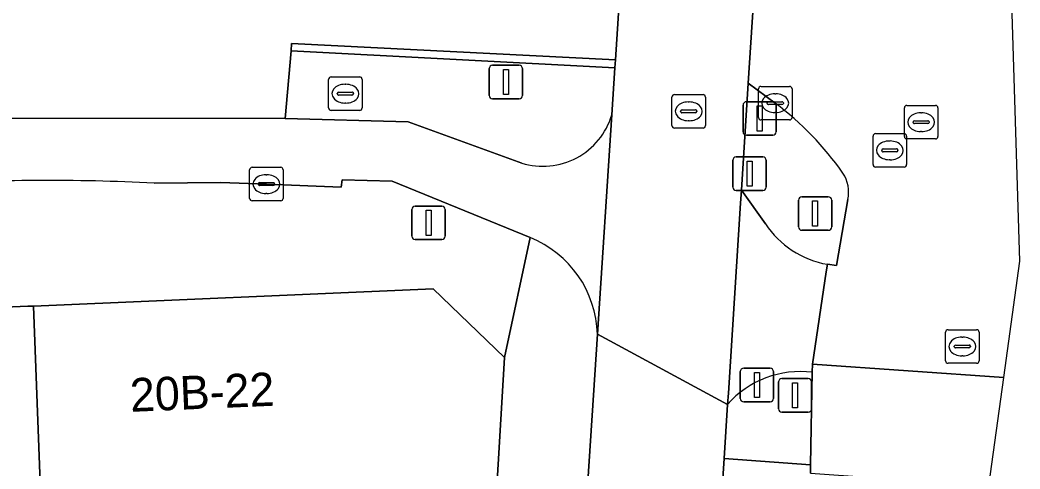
# Model space of a CAD drawing. Extents: x 161087 to 161926, y 382572 to 383873.
# Drawn here: x 161847.36 to 161877.19, y 382826.69 to 382840.09 of the extents above; entities that cross this region are included whole.
import ezdxf

# ---------------------------------------------------------------- set-up
doc = ezdxf.new("R2010")
doc.units = 0
for name, color, linetype in [('IMGEO_Berm_groen', 7, 'Continuous'), ('IMGEO_Drukknoppaal', 7, 'Continuous'), ('IMGEO_Fietspad_gesloten', 7, 'Continuous'), ('IMGEO_Kolk', 7, 'Continuous'), ('IMGEO_Lichtmast', 7, 'Continuous'), ('IMGEO_Pand', 7, 'Continuous'), ('IMGEO_Pand_nummerreeks', 7, 'Continuous'), ('IMGEO_Portaal', 7, 'Continuous'), ('IMGEO_Rijbaan_lokaal_gesloten', 7, 'Continuous'), ('IMGEO_Rijbaan_lokaal_open', 7, 'Continuous'), ('IMGEO_Rioolput', 7, 'Continuous'), ('IMGEO_Verkeerseiland_gesloten', 7, 'Continuous'), ('IMGEO_Verkeerseiland_open', 7, 'Continuous'), ('IMGEO_Verkeersregelinstallatiepaal', 7, 'Continuous'), ('IMGEO_Voetpad_open', 7, 'Continuous')]:
    doc.layers.add(name, color=color, linetype=linetype)

msp = doc.modelspace()

# ---------------------------------------------------------------- linework, layer by layer
at = {"layer": 'IMGEO_Berm_groen'}
msp.add_lwpolyline([(161870.941, 382826.561), (161870.946, 382826.819), (161868.362, 382827.004), (161866.09, 382792.42), (161866.022, 382791.413), (161868.117, 382791.28), (161868.615, 382791.249), (161868.901, 382795.776), (161869.763, 382809.058)], dxfattribs=at)
at = {"layer": 'IMGEO_Drukknoppaal'}
for p, q in [((161868.629, 382835.1), (161868.629, 382835.9)), ((161868.629, 382835.9), (161868.629, 382835.1)), ((161868.729, 382836), (161869.519, 382836)), ((161869.519, 382836), (161868.729, 382836)), ((161869.619, 382835.9), (161869.619, 382835.1)), ((161869.619, 382835.1), (161869.619, 382835.9)), ((161869.519, 382835), (161868.729, 382835)), ((161868.729, 382835), (161869.519, 382835)), ((161868.949, 382829.695), (161869.739, 382829.695)), ((161869.739, 382829.695), (161868.949, 382829.695)), ((161868.849, 382828.795), (161868.849, 382829.595)), ((161868.849, 382829.595), (161868.849, 382828.795)), ((161869.839, 382829.595), (161869.839, 382828.795)), ((161869.839, 382828.795), (161869.839, 382829.595)), ((161869.739, 382828.695), (161868.949, 382828.695)), ((161868.949, 382828.695), (161869.739, 382828.695))]:
    msp.add_line(p, q, dxfattribs=at)
for points in [[(161869.049, 382835.875), (161869.199, 382835.875), (161869.199, 382835.125), (161869.049, 382835.125), (161869.049, 382835.875)], [(161869.269, 382829.57), (161869.419, 382829.57), (161869.419, 382828.82), (161869.269, 382828.82), (161869.269, 382829.57)]]:
    msp.add_lwpolyline(points, dxfattribs=at)
for centre, start, end in [((161868.729, 382835.9), 90, 180), ((161868.729, 382835.9), 90, 180), ((161869.519, 382835.9), 0, 90), ((161869.519, 382835.9), 360, 90), ((161868.729, 382835.1), 180, 270), ((161868.729, 382835.1), 180, 270), ((161869.519, 382835.1), 270, 0), ((161869.519, 382835.1), 270, 0), ((161868.949, 382829.595), 90, 180), ((161868.949, 382829.595), 90, 180), ((161869.739, 382829.595), 0, 90), ((161869.739, 382829.595), 360, 90), ((161868.949, 382828.795), 180, 270), ((161868.949, 382828.795), 180, 270), ((161869.739, 382828.795), 270, 0), ((161869.739, 382828.795), 270, 0)]:
    msp.add_arc(centre, 0.1, start, end, dxfattribs=at)
at = {"layer": 'IMGEO_Fietspad_gesloten'}
for points in [[(161867.147, 382869.551), (161866.618, 382861.706), (161865.956, 382851.636), (161865.566, 382845.696), (161865.461, 382844.092), (161865.445, 382843.847), (161865.12, 382838.895), (161865.105, 382838.659), (161865.013, 382837.253), (161864.583, 382830.709), (161868.468, 382828.616), (161868.493, 382828.949), (161868.857, 382834.621), (161868.883, 382835.013), (161869.087, 382838.199), (161869.439, 382843.669), (161869.49, 382844.463)], [(161869.599, 382834.003), (161868.883, 382835.013), (161868.857, 382834.621), (161868.493, 382828.949), (161868.468, 382828.616)], [(161871.412, 382832.571), (161871.446, 382832.798)], [(161870.997, 382829.577), (161871.001, 382829.815), (161871.412, 382832.571)], [(161862.676, 382741.127), (161863.359, 382751.101), (161864.144, 382763.393), (161864.145, 382763.415), (161865.585, 382784.899), (161866.022, 382791.413), (161866.09, 382792.42), (161868.362, 382827.004), (161868.468, 382828.616), (161864.583, 382830.709), (161862.087, 382792.658), (161859.377, 382751.761), (161858.204, 382734.049)]]:
    msp.add_lwpolyline(points, dxfattribs=at)
for centre, radius, start, end in [((161871.929, 382835.557), 2.801, 213.6927, 260.0657), ((161870.644, 382826.697), 2.902, 83.0178, 138.595)]:
    msp.add_arc(centre, radius, start, end, dxfattribs=at)
at = {"layer": 'IMGEO_Kolk'}
for p, q in [((161869.391, 382837.18), (161869.391, 382838.032)), ((161869.466, 382838.106), (161870.318, 382838.106)), ((161870.392, 382838.032), (161870.392, 382837.18)), ((161869.879, 382837.886), (161869.904, 382837.886)), ((161869.65, 382837.6), (161869.65, 382837.612)), ((161870.088, 382837.563), (161869.69, 382837.563)), ((161869.693, 382837.649), (161870.091, 382837.649)), ((161870.134, 382837.612), (161870.134, 382837.6)), ((161870.318, 382837.106), (161869.466, 382837.106)), ((161869.902, 382837.326), (161869.877, 382837.326)), ((161854.208, 382834.765), (161854.208, 382835.617)), ((161854.283, 382835.691), (161855.135, 382835.691)), ((161855.209, 382835.617), (161855.209, 382834.765)), ((161854.696, 382835.471), (161854.721, 382835.471)), ((161854.467, 382835.185), (161854.467, 382835.197)), ((161854.905, 382835.148), (161854.507, 382835.148)), ((161854.51, 382835.234), (161854.908, 382835.234)), ((161854.951, 382835.197), (161854.951, 382835.185)), ((161855.135, 382834.691), (161854.283, 382834.691)), ((161854.719, 382834.911), (161854.694, 382834.911))]:
    msp.add_line(p, q, dxfattribs=at)
for points in [[(161869.391, 382837.18), (161869.391, 382838.032)], [(161869.466, 382838.106), (161870.318, 382838.106)], [(161870.392, 382838.032), (161870.392, 382837.18)], [(161870.318, 382837.106), (161869.466, 382837.106)], [(161854.208, 382834.765), (161854.208, 382835.617)], [(161854.283, 382835.691), (161855.135, 382835.691)], [(161855.209, 382835.617), (161855.209, 382834.765)], [(161855.135, 382834.691), (161854.283, 382834.691)]]:
    msp.add_lwpolyline(points, dxfattribs=at)
for centre, radius, start, end in [((161869.468, 382838.03), 0.0765, 91.552, 178.448), ((161869.468, 382838.03), 0.0765, 91.552, 178.448), ((161870.316, 382838.03), 0.0765, 1.552, 88.448), ((161870.316, 382838.03), 0.0765, 1.552, 88.448), ((161869.69, 382837.609), 0.0403, 85.8775, 175.7526), ((161869.687, 382837.599), 0.0366, 178.938, 274.7102), ((161870.091, 382837.606), 0.043, 264.8664, 352.4533), ((161870.095, 382837.611), 0.0386, 1.7309, 96.639), ((161869.468, 382837.182), 0.0765, 181.552, 268.448), ((161869.468, 382837.182), 0.0765, 181.552, 268.448), ((161870.316, 382837.182), 0.0765, 271.552, 358.448), ((161870.316, 382837.182), 0.0765, 271.552, 358.448), ((161854.285, 382835.615), 0.0765, 91.552, 178.448), ((161854.285, 382835.615), 0.0765, 91.552, 178.448), ((161855.133, 382835.615), 0.0765, 1.552, 88.448), ((161855.133, 382835.615), 0.0765, 1.552, 88.448), ((161854.507, 382835.194), 0.0403, 85.8775, 175.7526), ((161854.504, 382835.184), 0.0366, 178.938, 274.7102), ((161854.908, 382835.191), 0.043, 264.8664, 352.4533), ((161854.912, 382835.196), 0.0386, 1.7309, 96.639), ((161854.285, 382834.767), 0.0765, 181.552, 268.448), ((161854.285, 382834.767), 0.0765, 181.552, 268.448), ((161855.133, 382834.767), 0.0765, 271.552, 358.448), ((161855.133, 382834.767), 0.0765, 271.552, 358.448)]:
    msp.add_arc(centre, radius, start, end, dxfattribs=at)
for centre, major_axis, ratio, start_param, end_param in [((161869.878, 382837.606), (-0.387, 0.002), 0.722429, 4.712389, 7.853982), ((161869.903, 382837.606), (-0.39, 0.002), 0.717154, 1.570796, 4.712389), ((161854.695, 382835.191), (-0.387, 0.002), 0.722429, 4.712389, 7.853982), ((161854.72, 382835.191), (-0.39, 0.002), 0.717154, 1.570796, 4.712389)]:
    msp.add_ellipse(centre, major_axis=major_axis, ratio=ratio, start_param=start_param, end_param=end_param, dxfattribs=at)
at = {"layer": 'IMGEO_Lichtmast'}
for p, q in [((161859.051, 382833.635), (161859.051, 382834.435)), ((161859.051, 382834.435), (161859.051, 382833.635)), ((161859.151, 382834.535), (161859.941, 382834.535)), ((161859.941, 382834.535), (161859.151, 382834.535)), ((161860.041, 382834.435), (161860.041, 382833.635)), ((161860.041, 382833.635), (161860.041, 382834.435)), ((161859.941, 382833.535), (161859.151, 382833.535)), ((161859.151, 382833.535), (161859.941, 382833.535))]:
    msp.add_line(p, q, dxfattribs=at)
msp.add_lwpolyline([(161859.471, 382834.41), (161859.621, 382834.41), (161859.621, 382833.66), (161859.471, 382833.66), (161859.471, 382834.41)], dxfattribs=at)
for centre, start, end in [((161859.151, 382834.435), 90, 180), ((161859.151, 382834.435), 90, 180), ((161859.941, 382834.435), 0, 90), ((161859.941, 382834.435), 360, 90), ((161859.151, 382833.635), 180, 270), ((161859.151, 382833.635), 180, 270), ((161859.941, 382833.635), 270, 0), ((161859.941, 382833.635), 270, 0)]:
    msp.add_arc(centre, 0.1, start, end, dxfattribs=at)
at = {"layer": 'IMGEO_Pand'}
for points in [[(161861.514, 382824.987), (161861.808, 382830.019), (161859.687, 382832.064), (161847.76, 382831.552), (161848.168, 382820.764), (161852.005, 382813.152), (161855.823, 382805.577), (161860.365, 382805.353)], [(161848.168, 382820.764), (161847.76, 382831.552), (161847.588, 382831.545), (161836.688, 382831.067), (161836.95, 382824.507), (161837.245, 382817.14), (161841.698, 382808.077), (161842.133, 382808.291), (161851.488, 382812.897), (161852.005, 382813.152)]]:
    msp.add_lwpolyline(points, close=True, dxfattribs=at)
at = {"layer": 'IMGEO_Portaal'}
for p, q in [((161870.585, 382833.912), (161870.585, 382834.712)), ((161870.585, 382834.712), (161870.585, 382833.912)), ((161870.685, 382834.812), (161871.475, 382834.812)), ((161871.475, 382834.812), (161870.685, 382834.812)), ((161871.575, 382834.712), (161871.575, 382833.912)), ((161871.575, 382833.912), (161871.575, 382834.712)), ((161871.475, 382833.812), (161870.685, 382833.812)), ((161870.685, 382833.812), (161871.475, 382833.812))]:
    msp.add_line(p, q, dxfattribs=at)
msp.add_lwpolyline([(161871.005, 382834.687), (161871.155, 382834.687), (161871.155, 382833.937), (161871.005, 382833.937), (161871.005, 382834.687)], dxfattribs=at)
for centre, start, end in [((161870.685, 382834.712), 90, 180), ((161870.685, 382834.712), 90, 180), ((161871.475, 382834.712), 0, 90), ((161871.475, 382834.712), 360, 90), ((161870.685, 382833.912), 180, 270), ((161870.685, 382833.912), 180, 270), ((161871.475, 382833.912), 270, 0), ((161871.475, 382833.912), 270, 0)]:
    msp.add_arc(centre, 0.1, start, end, dxfattribs=at)
at = {"layer": 'IMGEO_Rijbaan_lokaal_gesloten'}
for points in [[(161876.715, 382829.422), (161877.194, 382832.895), (161876.775, 382846.401), (161874.332, 382846.716), (161872.9, 382846.911)], [(161870.19, 382843.957), (161869.439, 382843.669), (161869.087, 382838.199), (161869.892, 382837.606)], [(161841.766, 382837.156), (161855.272, 382837.15), (161855.451, 382839.166), (161855.46, 382839.39), (161865.12, 382838.895), (161865.445, 382843.847), (161862.497, 382843.541)], [(161862.326, 382835.817), (161858.94, 382837.052), (161855.272, 382837.15), (161841.766, 382837.156), (161826.222, 382836.445), (161795.133, 382834.857), (161788.346, 382834.584), (161784.515, 382834.256), (161779.972, 382833.544), (161774.717, 382832.23), (161767.109, 382829.547), (161737.362, 382819.209), (161737.856, 382817.95), (161766.768, 382827.835), (161768.826, 382828.505), (161772.113, 382829.631)], [(161864.583, 382830.709), (161865.013, 382837.253)], [(161851.361, 382835.214), (161853.352, 382835.234), (161854.709, 382835.191), (161856.94, 382835.098), (161856.964, 382835.313), (161858.458, 382835.275), (161862.575, 382833.596)], [(161872.056, 382834.73), (161871.714, 382832.765), (161871.446, 382832.798), (161871.412, 382832.571), (161871.001, 382829.815), (161876.715, 382829.422)]]:
    msp.add_lwpolyline(points, dxfattribs=at)
msp.add_lwpolyline([(161855.451, 382839.166), (161865.105, 382838.659), (161865.12, 382838.895), (161855.46, 382839.39)], close=True, dxfattribs=at)
for centre, radius, start, end in [((161864.343, 382830.225), 9.234, 34.957, 53.0632), ((161862.959, 382837.864), 2.143, 252.8122, 343.4301), ((161848.201, 382777.912), 57.389, 86.84331, 93.8584), ((161871.065, 382834.954), 1.016, 347.2928, 33.6118), ((161861.385, 382830.626), 3.2, 1.4829, 68.1568)]:
    msp.add_arc(centre, radius, start, end, dxfattribs=at)
at = {"layer": 'IMGEO_Rijbaan_lokaal_open'}
msp.add_lwpolyline([(161876.269, 382826.189), (161876.715, 382829.422), (161871.001, 382829.815), (161870.997, 382829.577), (161870.946, 382826.819), (161870.941, 382826.561), (161876.269, 382826.189)], dxfattribs=at)
at = {"layer": 'IMGEO_Rioolput'}
for p, q in [((161856.565, 382837.463), (161856.565, 382838.315)), ((161856.64, 382838.389), (161857.492, 382838.389)), ((161857.566, 382838.315), (161857.566, 382837.463)), ((161857.053, 382838.169), (161857.078, 382838.169)), ((161856.824, 382837.883), (161856.824, 382837.895)), ((161857.262, 382837.846), (161856.864, 382837.846)), ((161856.867, 382837.932), (161857.265, 382837.932)), ((161857.308, 382837.895), (161857.308, 382837.883)), ((161866.809, 382836.936), (161866.809, 382837.788)), ((161866.884, 382837.862), (161867.736, 382837.862)), ((161867.81, 382837.788), (161867.81, 382836.936)), ((161857.492, 382837.389), (161856.64, 382837.389)), ((161857.076, 382837.609), (161857.051, 382837.609)), ((161867.068, 382837.356), (161867.068, 382837.368)), ((161867.111, 382837.405), (161867.509, 382837.405)), ((161867.297, 382837.642), (161867.322, 382837.642)), ((161867.552, 382837.368), (161867.552, 382837.356)), ((161873.743, 382836.612), (161873.743, 382837.464)), ((161873.818, 382837.538), (161874.67, 382837.538)), ((161874.744, 382837.464), (161874.744, 382836.612)), ((161867.506, 382837.319), (161867.108, 382837.319)), ((161867.32, 382837.082), (161867.295, 382837.082)), ((161874.045, 382837.081), (161874.443, 382837.081)), ((161874.231, 382837.318), (161874.256, 382837.318)), ((161867.736, 382836.862), (161866.884, 382836.862)), ((161874.002, 382837.032), (161874.002, 382837.044)), ((161874.44, 382836.995), (161874.042, 382836.995)), ((161874.254, 382836.758), (161874.229, 382836.758)), ((161874.486, 382837.044), (161874.486, 382837.032)), ((161872.809, 382835.771), (161872.809, 382836.623)), ((161872.884, 382836.697), (161873.736, 382836.697)), ((161873.297, 382836.477), (161873.322, 382836.477)), ((161873.81, 382836.623), (161873.81, 382835.771)), ((161874.67, 382836.538), (161873.818, 382836.538)), ((161873.068, 382836.191), (161873.068, 382836.203)), ((161873.111, 382836.24), (161873.509, 382836.24)), ((161873.552, 382836.203), (161873.552, 382836.191)), ((161873.506, 382836.154), (161873.108, 382836.154)), ((161873.32, 382835.917), (161873.295, 382835.917)), ((161873.736, 382835.697), (161872.884, 382835.697)), ((161875.048, 382830.846), (161875.9, 382830.846)), ((161874.973, 382829.92), (161874.973, 382830.772)), ((161875.461, 382830.626), (161875.486, 382830.626)), ((161875.974, 382830.772), (161875.974, 382829.92)), ((161875.232, 382830.34), (161875.232, 382830.352)), ((161875.67, 382830.303), (161875.272, 382830.303)), ((161875.275, 382830.389), (161875.673, 382830.389)), ((161875.716, 382830.352), (161875.716, 382830.34)), ((161875.484, 382830.066), (161875.459, 382830.066)), ((161875.9, 382829.846), (161875.048, 382829.846))]:
    msp.add_line(p, q, dxfattribs=at)
for points in [[(161856.565, 382837.463), (161856.565, 382838.315)], [(161856.64, 382838.389), (161857.492, 382838.389)], [(161857.566, 382838.315), (161857.566, 382837.463)], [(161866.809, 382836.936), (161866.809, 382837.788)], [(161866.884, 382837.862), (161867.736, 382837.862)], [(161867.81, 382837.788), (161867.81, 382836.936)], [(161857.492, 382837.389), (161856.64, 382837.389)], [(161873.743, 382836.612), (161873.743, 382837.464)], [(161873.818, 382837.538), (161874.67, 382837.538)], [(161874.744, 382837.464), (161874.744, 382836.612)], [(161867.736, 382836.862), (161866.884, 382836.862)], [(161872.809, 382835.771), (161872.809, 382836.623)], [(161872.884, 382836.697), (161873.736, 382836.697)], [(161873.81, 382836.623), (161873.81, 382835.771)], [(161874.67, 382836.538), (161873.818, 382836.538)], [(161873.736, 382835.697), (161872.884, 382835.697)], [(161875.048, 382830.846), (161875.9, 382830.846)], [(161874.973, 382829.92), (161874.973, 382830.772)], [(161875.974, 382830.772), (161875.974, 382829.92)], [(161875.9, 382829.846), (161875.048, 382829.846)]]:
    msp.add_lwpolyline(points, dxfattribs=at)
for centre, radius, start, end in [((161856.642, 382838.313), 0.0765, 91.552, 178.448), ((161856.642, 382838.313), 0.0765, 91.552, 178.448), ((161857.49, 382838.313), 0.0765, 1.552, 88.448), ((161857.49, 382838.313), 0.0765, 1.552, 88.448), ((161856.864, 382837.892), 0.0403, 85.8775, 175.7526), ((161856.861, 382837.882), 0.0366, 178.938, 274.7102), ((161857.265, 382837.889), 0.043, 264.8664, 352.4533), ((161857.269, 382837.894), 0.0386, 1.7309, 96.639), ((161866.886, 382837.786), 0.0765, 91.552, 178.448), ((161866.886, 382837.786), 0.0765, 91.552, 178.448), ((161867.734, 382837.786), 0.0765, 1.552, 88.448), ((161867.734, 382837.786), 0.0765, 1.552, 88.448), ((161856.642, 382837.465), 0.0765, 181.552, 268.448), ((161856.642, 382837.465), 0.0765, 181.552, 268.448), ((161857.49, 382837.465), 0.0765, 271.552, 358.448), ((161857.49, 382837.465), 0.0765, 271.552, 358.448), ((161867.108, 382837.365), 0.0403, 85.8775, 175.7526), ((161867.105, 382837.355), 0.0366, 178.938, 274.7102), ((161867.509, 382837.362), 0.043, 264.8664, 352.4533), ((161867.513, 382837.367), 0.0386, 1.7309, 96.639), ((161873.82, 382837.462), 0.0765, 91.552, 178.448), ((161873.82, 382837.462), 0.0765, 91.552, 178.448), ((161874.668, 382837.462), 0.0765, 1.552, 88.448), ((161874.668, 382837.462), 0.0765, 1.552, 88.448), ((161874.042, 382837.041), 0.0403, 85.8775, 175.7526), ((161874.447, 382837.043), 0.0386, 1.7309, 96.639), ((161866.886, 382836.938), 0.0765, 181.552, 268.448), ((161866.886, 382836.938), 0.0765, 181.552, 268.448), ((161867.734, 382836.938), 0.0765, 271.552, 358.448), ((161867.734, 382836.938), 0.0765, 271.552, 358.448), ((161874.039, 382837.031), 0.0366, 178.938, 274.7102), ((161874.443, 382837.038), 0.043, 264.8664, 352.4533), ((161872.886, 382836.621), 0.0765, 91.552, 178.448), ((161872.886, 382836.621), 0.0765, 91.552, 178.448), ((161873.734, 382836.621), 0.0765, 1.552, 88.448), ((161873.734, 382836.621), 0.0765, 1.552, 88.448), ((161873.82, 382836.614), 0.0765, 181.552, 268.448), ((161873.82, 382836.614), 0.0765, 181.552, 268.448), ((161874.668, 382836.614), 0.0765, 271.552, 358.448), ((161874.668, 382836.614), 0.0765, 271.552, 358.448), ((161873.108, 382836.2), 0.0403, 85.8775, 175.7526), ((161873.105, 382836.19), 0.0366, 178.938, 274.7102), ((161873.509, 382836.197), 0.043, 264.8664, 352.4533), ((161873.513, 382836.202), 0.0386, 1.7309, 96.639), ((161872.886, 382835.773), 0.0765, 181.552, 268.448), ((161872.886, 382835.773), 0.0765, 181.552, 268.448), ((161873.734, 382835.773), 0.0765, 271.552, 358.448), ((161873.734, 382835.773), 0.0765, 271.552, 358.448), ((161875.05, 382830.77), 0.0765, 91.552, 178.448), ((161875.05, 382830.77), 0.0765, 91.552, 178.448), ((161875.898, 382830.77), 0.0765, 1.552, 88.448), ((161875.898, 382830.77), 0.0765, 1.552, 88.448), ((161875.272, 382830.349), 0.0403, 85.8775, 175.7526), ((161875.269, 382830.339), 0.0366, 178.938, 274.7102), ((161875.673, 382830.346), 0.043, 264.8664, 352.4533), ((161875.677, 382830.351), 0.0386, 1.7309, 96.639), ((161875.05, 382829.922), 0.0765, 181.552, 268.448), ((161875.05, 382829.922), 0.0765, 181.552, 268.448), ((161875.898, 382829.922), 0.0765, 271.552, 358.448), ((161875.898, 382829.922), 0.0765, 271.552, 358.448)]:
    msp.add_arc(centre, radius, start, end, dxfattribs=at)
for centre, major_axis, ratio, start_param, end_param in [((161857.052, 382837.889), (-0.387, 0.002), 0.722429, 4.712389, 7.853982), ((161857.077, 382837.889), (-0.39, 0.002), 0.717154, 1.570796, 4.712389), ((161867.296, 382837.362), (-0.387, 0.002), 0.722429, 4.712389, 7.853982), ((161867.321, 382837.362), (-0.39, 0.002), 0.717154, 1.570796, 4.712389), ((161874.23, 382837.038), (-0.387, 0.002), 0.722429, 4.712389, 7.853982), ((161874.255, 382837.038), (-0.39, 0.002), 0.717154, 1.570796, 4.712389), ((161873.296, 382836.197), (-0.387, 0.002), 0.722429, 4.712389, 7.853982), ((161873.321, 382836.197), (-0.39, 0.002), 0.717154, 1.570796, 4.712389), ((161875.46, 382830.346), (-0.387, 0.002), 0.722429, 4.712389, 7.853982), ((161875.485, 382830.346), (-0.39, 0.002), 0.717154, 1.570796, 4.712389)]:
    msp.add_ellipse(centre, major_axis=major_axis, ratio=ratio, start_param=start_param, end_param=end_param, dxfattribs=at)
at = {"layer": 'IMGEO_Verkeerseiland_gesloten'}
for points in [[(161869.087, 382838.199), (161868.883, 382835.013), (161869.599, 382834.003)], [(161869.892, 382837.606), (161869.087, 382838.199)], [(161871.446, 382832.798), (161871.714, 382832.765), (161872.056, 382834.73)]]:
    msp.add_lwpolyline(points, dxfattribs=at)
for centre, radius, start, end in [((161864.343, 382830.225), 9.234, 34.957, 53.0632), ((161871.065, 382834.954), 1.016, 347.2928, 33.6118), ((161871.929, 382835.557), 2.801, 213.6927, 260.0657)]:
    msp.add_arc(centre, radius, start, end, dxfattribs=at)
at = {"layer": 'IMGEO_Verkeerseiland_open'}
for points in [[(161865.105, 382838.659), (161855.451, 382839.166), (161855.272, 382837.15), (161858.94, 382837.052), (161862.326, 382835.817)], [(161865.013, 382837.253), (161865.105, 382838.659)], [(161868.468, 382828.616), (161868.362, 382827.004), (161870.946, 382826.819), (161870.997, 382829.577)]]:
    msp.add_lwpolyline(points, dxfattribs=at)
for centre, radius, start, end in [((161862.959, 382837.864), 2.143, 252.8122, 343.4301), ((161870.644, 382826.697), 2.902, 83.0178, 138.595)]:
    msp.add_arc(centre, radius, start, end, dxfattribs=at)
at = {"layer": 'IMGEO_Verkeersregelinstallatiepaal'}
for p, q in [((161861.358, 382837.835), (161861.358, 382838.635)), ((161861.358, 382838.635), (161861.358, 382837.835)), ((161861.458, 382838.735), (161862.248, 382838.735)), ((161862.248, 382838.735), (161861.458, 382838.735)), ((161862.348, 382838.635), (161862.348, 382837.835)), ((161862.348, 382837.835), (161862.348, 382838.635)), ((161862.248, 382837.735), (161861.458, 382837.735)), ((161861.458, 382837.735), (161862.248, 382837.735)), ((161868.93, 382836.749), (161868.93, 382837.549)), ((161868.93, 382837.549), (161868.93, 382836.749)), ((161869.03, 382837.649), (161869.82, 382837.649)), ((161869.82, 382837.649), (161869.03, 382837.649)), ((161869.92, 382837.549), (161869.92, 382836.749)), ((161869.92, 382836.749), (161869.92, 382837.549)), ((161869.82, 382836.649), (161869.03, 382836.649)), ((161869.03, 382836.649), (161869.82, 382836.649)), ((161870.086, 382829.386), (161870.876, 382829.386)), ((161870.876, 382829.386), (161870.086, 382829.386)), ((161869.986, 382828.486), (161869.986, 382829.286)), ((161869.986, 382829.286), (161869.986, 382828.486)), ((161870.976, 382829.286), (161870.976, 382828.486)), ((161870.976, 382828.486), (161870.976, 382829.286)), ((161870.876, 382828.386), (161870.086, 382828.386)), ((161870.086, 382828.386), (161870.876, 382828.386))]:
    msp.add_line(p, q, dxfattribs=at)
for points in [[(161861.778, 382838.61), (161861.928, 382838.61), (161861.928, 382837.86), (161861.778, 382837.86), (161861.778, 382838.61)], [(161869.35, 382837.524), (161869.5, 382837.524), (161869.5, 382836.774), (161869.35, 382836.774), (161869.35, 382837.524)], [(161870.406, 382829.261), (161870.556, 382829.261), (161870.556, 382828.511), (161870.406, 382828.511), (161870.406, 382829.261)]]:
    msp.add_lwpolyline(points, dxfattribs=at)
for centre, start, end in [((161861.458, 382838.635), 90, 180), ((161861.458, 382838.635), 90, 180), ((161862.248, 382838.635), 0, 90), ((161862.248, 382838.635), 360, 90), ((161861.458, 382837.835), 180, 270), ((161861.458, 382837.835), 180, 270), ((161862.248, 382837.835), 270, 0), ((161862.248, 382837.835), 270, 0), ((161869.03, 382837.549), 90, 180), ((161869.03, 382837.549), 90, 180), ((161869.82, 382837.549), 0, 90), ((161869.82, 382837.549), 360, 90), ((161869.03, 382836.749), 180, 270), ((161869.03, 382836.749), 180, 270), ((161869.82, 382836.749), 270, 0), ((161869.82, 382836.749), 270, 0), ((161870.086, 382829.286), 90, 180), ((161870.086, 382829.286), 90, 180), ((161870.876, 382829.286), 0, 90), ((161870.876, 382829.286), 360, 90), ((161870.086, 382828.486), 180, 270), ((161870.086, 382828.486), 180, 270), ((161870.876, 382828.486), 270, 0), ((161870.876, 382828.486), 270, 0)]:
    msp.add_arc(centre, 0.1, start, end, dxfattribs=at)
at = {"layer": 'IMGEO_Voetpad_open'}
for points in [[(161862.575, 382833.596), (161858.458, 382835.275), (161856.964, 382835.313), (161856.94, 382835.098), (161854.709, 382835.191), (161853.352, 382835.234), (161851.361, 382835.214)], [(161790.746, 382829.084), (161800.329, 382829.386), (161800.928, 382829.412), (161800.95, 382828.783), (161805.053, 382829.003), (161822.916, 382829.848), (161829.775, 382830.173), (161829.74, 382830.675), (161832.463, 382830.793), (161836.688, 382831.067), (161847.588, 382831.545), (161847.76, 382831.552), (161859.687, 382832.064), (161861.808, 382830.019), (161862.575, 382833.596)], [(161862.575, 382833.596), (161861.808, 382830.019), (161861.514, 382824.987), (161860.365, 382805.353), (161860.305, 382804.076), (161859.631, 382791.892), (161859.25, 382785.386), (161859.223, 382784.937), (161858.54, 382773.49), (161857.067, 382750)], [(161858.204, 382734.049), (161859.377, 382751.761), (161862.087, 382792.658), (161864.583, 382830.709)]]:
    msp.add_lwpolyline(points, dxfattribs=at)
for centre, radius, start, end in [((161848.201, 382777.912), 57.389, 86.84331, 93.8584), ((161861.385, 382830.626), 3.2, 1.4829, 68.1568)]:
    msp.add_arc(centre, radius, start, end, dxfattribs=at)

# ---------------------------------------------------------------- texts
at = {"layer": 'IMGEO_Pand_nummerreeks'}
msp.add_text('20B-22', height=1, rotation=2.458, dxfattribs=at).set_placement((161850.658, 382828.394))

doc.saveas('drawing.dxf')
